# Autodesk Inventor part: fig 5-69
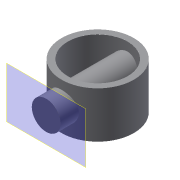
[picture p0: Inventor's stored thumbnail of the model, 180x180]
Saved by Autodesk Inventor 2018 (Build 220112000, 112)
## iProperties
Shininess: 64.0
Length Units: 11269
Angle Units: 11279
Time Units: 11290
Mass Units: 11283
Length Display Precision: 3
Angle Display Precision: 2
Compacted: True
Part Number: fig 5-69
Document SubType Name: Modeling
Created: 2002-12
Designer: deepak
Density: 1 g/cm^3
Material: Generic
Appearance: Default
Density: 0.0
Volumn: 0.0
Area: 0.0
PropertySet Name: Model Information
Control State: 0
Master: False
Checked Out: False
Author: deepak
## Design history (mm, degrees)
sketch "Sketch1"
  geometry: C1 r 23.454 at (0, 0); C2 r 19.43 at (0, 0)
  constraints: 2 centre point, 1 coincident, 1 concentric
extrude "Extrusion1" new body sketch "Sketch1" stored distance "d0" = 30; taper "d1" = 0 deg
workplane "Work Plane1"
workplane "Work Plane2"
sketch "Sketch2"
  geometry: C1 r 9.343 at (0, 0)
  constraints: 1 centre point
extrude "Extrusion2" join sketch "Sketch2" stored distance "d4" = 10; taper "d5" = 0 deg
body "Solid1"
